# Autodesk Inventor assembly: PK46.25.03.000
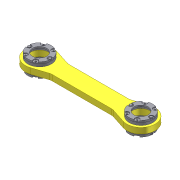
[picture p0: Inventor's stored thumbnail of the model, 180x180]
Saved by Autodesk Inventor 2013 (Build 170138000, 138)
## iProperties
Created: 2005-04
Part Number: PK46.25.03.000
Document SubType Name: Assembly
Designer: salex
Manufacturer: Standard
Standards Organization: Custom
Author: salex
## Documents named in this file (6)
- C:\Product Design Suite 2013 Test Drive\Dynamic Simulation\Workspace\Assy, Chassis, Front\PK46.25.03.000.iam
- C:\Product Design Suite 2013 Test Drive\Dynamic Simulation\Workspace\Assy, Chassis, Front\PK46.25.03.010.iam
- C:\Product Design Suite 2013 Test Drive\Dynamic Simulation\Workspace\Assy, Chassis, Front\PK46.25.01.014.ipt
- C:\Product Design Suite 2013 Test Drive\Dynamic Simulation\Workspace\Assy, Chassis, Front\PK46.25.01.015.ipt
- C:\Product Design Suite 2013 Test Drive\Dynamic Simulation\Workspace\Assy, Chassis, Front\M10-6H.5.019(S16).ipt
- C:\Product Design Suite 2013 Test Drive\Dynamic Simulation\Workspace\Assy, Chassis, Front\10.65G.019.ipt
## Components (17 placed, 5 different names)
1. PK46.25.03.010:1 [sub-assembly] — Вставка:1, Вставка:2, Вставка:3, Вставка:4, Совмещение:1, Совмещение:2, Совмещение:3, Совмещение:4, Угол:1, Угол:2, Угол:3, Угол:4
2. PK46.25.01.014:1 — Вставка:1, Совмещение:1, Вставка:14, Вставка:13
3. PK46.25.01.014:2 — Вставка:2, Совмещение:2, Вставка:5, Вставка:6
4. PK46.25.01.014:3 — Вставка:4, Совмещение:4, Вставка:15, Вставка:16
5. PK46.25.01.014:4 — Вставка:3, Совмещение:3, Вставка:10, Вставка:9
6. PK46.25.01.015:1 — Вставка:13
7. PK46.25.01.015:2 — Вставка:14
8. PK46.25.01.015:3 — Вставка:6
9. PK46.25.01.015:4 — Вставка:5
10. M10-6H.5.019(S16):1 — Вставка:12, Угол:2
11. M10-6H.5.019(S16):2 — Вставка:11, Угол:1
12. M10-6H.5.019(S16):3 — Вставка:7, Угол:4
13. M10-6H.5.019(S16):4 — Вставка:8, Угол:3
14. 10.65G.019:1 — Вставка:12, Вставка:15
15. 10.65G.019:2 — Вставка:11, Вставка:16
16. 10.65G.019:3 — Вставка:7, Вставка:9
17. 10.65G.019:4 — Вставка:8, Вставка:10
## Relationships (24: Insert 16, Mate 4, Angle 4)
- Вставка:1 [Insert]: PK46.25.03.010:1 ↔ PK46.25.01.014:1
- Вставка:2 [Insert]: PK46.25.03.010:1 ↔ PK46.25.01.014:2
- Вставка:3 [Insert]: PK46.25.03.010:1 ↔ PK46.25.01.014:4
- Вставка:4 [Insert]: PK46.25.03.010:1 ↔ PK46.25.01.014:3
- Совмещение:1 [Mate]: PK46.25.03.010:1 ↔ PK46.25.01.014:1
- Совмещение:2 [Mate]: PK46.25.03.010:1 ↔ PK46.25.01.014:2
- Совмещение:3 [Mate]: PK46.25.03.010:1 ↔ PK46.25.01.014:4
- Совмещение:4 [Mate]: PK46.25.03.010:1 ↔ PK46.25.01.014:3
- Вставка:7 [Insert]: M10-6H.5.019(S16):3 ↔ 10.65G.019:3
- Вставка:8 [Insert]: M10-6H.5.019(S16):4 ↔ 10.65G.019:4
- Вставка:11 [Insert]: M10-6H.5.019(S16):2 ↔ 10.65G.019:2
- Вставка:12 [Insert]: M10-6H.5.019(S16):1 ↔ 10.65G.019:1
- Угол:1 [Angle]: PK46.25.03.010:1 ↔ M10-6H.5.019(S16):2
- Угол:2 [Angle]: PK46.25.03.010:1 ↔ M10-6H.5.019(S16):1
- Угол:3 [Angle]: PK46.25.03.010:1 ↔ M10-6H.5.019(S16):4
- Угол:4 [Angle]: PK46.25.03.010:1 ↔ M10-6H.5.019(S16):3
- Вставка:5 [Insert]: PK46.25.01.014:2 ↔ PK46.25.01.015:4
- Вставка:6 [Insert]: PK46.25.01.014:2 ↔ PK46.25.01.015:3
- Вставка:14 [Insert]: PK46.25.01.014:1 ↔ PK46.25.01.015:2
- Вставка:13 [Insert]: PK46.25.01.014:1 ↔ PK46.25.01.015:1
- Вставка:15 [Insert]: PK46.25.01.014:3 ↔ 10.65G.019:1
- Вставка:16 [Insert]: PK46.25.01.014:3 ↔ 10.65G.019:2
- Вставка:10 [Insert]: PK46.25.01.014:4 ↔ 10.65G.019:4
- Вставка:9 [Insert]: PK46.25.01.014:4 ↔ 10.65G.019:3
